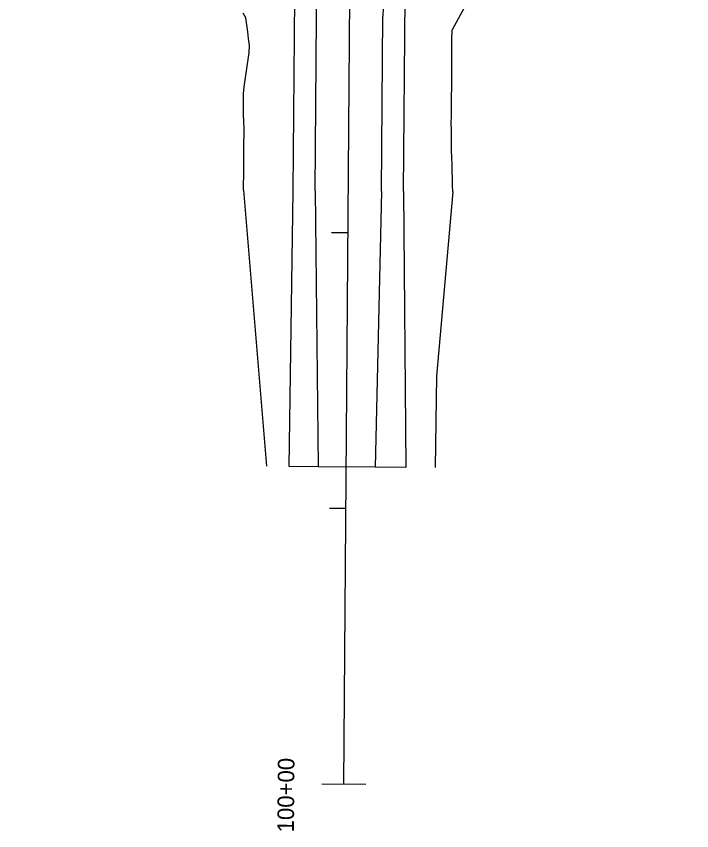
# Model space of a CAD drawing. Extents: x 1311167 to 1314552, y 2087587 to 2090602.
# Drawn here: x 1313869.5 to 1314114.4, y 2087983.8 to 2088279.1 of the extents above; entities that cross this region are included whole.
import ezdxf

# ---------------------------------------------------------------- set-up
doc = ezdxf.new("R2010")
doc.units = 0
for name, color, linetype in [('R_Bridge', 7, 'Continuous'), ('R_Horz Alg Stationing', 7, 'Continuous'), ('R_Proposed Road', 7, 'Continuous'), ('S_EDGE_CONCRETE', 7, 'Continuous'), ('S_EDGE_PAVEMENT', 7, 'Continuous'), ('S_PAVEMENT_CROWN', 7, 'Continuous')]:
    doc.layers.add(name, color=color, linetype=linetype)

msp = doc.modelspace()

# ---------------------------------------------------------------- linework, layer by layer
at = {"layer": 'R_Bridge'}
for points in [[(1313983.85, 2088200.74), (1313989.85, 2088200.69)], [(1313983.08, 2088100.74), (1313989.08, 2088100.7)], [(1313980.32, 2088000.76), (1313996.32, 2088000.64)]]:
    msp.add_lwpolyline(points, dxfattribs=at)
at = {"layer": 'R_Horz Alg Stationing'}
msp.add_line((1313988.32, 2088000.7), (1313997.14, 2089155.24), dxfattribs=at)
at = {"layer": 'R_Proposed Road'}
msp.add_line((1313988.32, 2088000.7), (1313992.17, 2088504.92), dxfattribs=at)
at = {"layer": 'S_EDGE_CONCRETE'}
for p, q in [((1314035.5, 2088288.69), (1314027.56, 2088274.13)), ((1313951.88, 2088215.98), (1313960.25, 2088115.92))]:
    msp.add_line(p, q, dxfattribs=at)
for points in [[(1313951.88, 2088215.98), (1313951.97, 2088218.48), (1313951.99, 2088220.98), (1313952.02, 2088223.48), (1313952.04, 2088225.98), (1313952.06, 2088228.48), (1313952.08, 2088230.98), (1313952.1, 2088233.48), (1313952.12, 2088235.98), (1313952.13, 2088238.48), (1313952.02, 2088240.98), (1313951.95, 2088243.48), (1313951.96, 2088245.98), (1313951.96, 2088248.48), (1313951.97, 2088250.98), (1313952.12, 2088253.48), (1313952.49, 2088255.98), (1313952.86, 2088258.48), (1313953.22, 2088260.98), (1313953.58, 2088263.47), (1313953.94, 2088265.97), (1313954.1, 2088268.47), (1313953.78, 2088270.97), (1313953.47, 2088273.47), (1313953.15, 2088275.98), (1313952.83, 2088278.48), (1313951.77, 2088280.22)], [(1314027.83, 2088215.4), (1314027.75, 2088217.9), (1314027.67, 2088220.41), (1314027.6, 2088222.91), (1314027.53, 2088225.41), (1314027.45, 2088227.91), (1314027.38, 2088230.41), (1314027.35, 2088232.91), (1314027.32, 2088235.41), (1314027.29, 2088237.91), (1314027.27, 2088240.41), (1314027.3, 2088242.91), (1314027.33, 2088245.41), (1314027.36, 2088247.91), (1314027.4, 2088250.41), (1314027.43, 2088252.91), (1314027.47, 2088255.41), (1314027.49, 2088257.91), (1314027.49, 2088260.41), (1314027.5, 2088262.91), (1314027.5, 2088265.41), (1314027.51, 2088267.91), (1314027.52, 2088270.41), (1314027.56, 2088274.13)], [(1314027.83, 2088215.4), (1314021.86, 2088148.65), (1314021.38, 2088115.45)]]:
    msp.add_lwpolyline(points, dxfattribs=at)
at = {"layer": 'S_EDGE_PAVEMENT'}
for p, q in [((1313969.96, 2088215.85), (1313970.61, 2088300.36)), ((1314009.96, 2088215.54), (1314010.61, 2088300.74)), ((1313968.44, 2088115.85), (1313969.96, 2088215.85)), ((1314009.96, 2088215.54), (1314010.82, 2088115.53)), ((1313979.04, 2088115.77), (1313968.44, 2088115.85)), ((1314010.82, 2088115.53), (1313999.62, 2088115.62))]:
    msp.add_line(p, q, dxfattribs=at)
at = {"layer": 'S_PAVEMENT_CROWN'}
for p, q in [((1313977.96, 2088215.79), (1313978.44, 2088278.57)), ((1314001.96, 2088215.6), (1314002.45, 2088279.08)), ((1313977.96, 2088215.79), (1313979.04, 2088115.77)), ((1314001.96, 2088215.6), (1313999.62, 2088115.62)), ((1313999.62, 2088115.62), (1313979.04, 2088115.77))]:
    msp.add_line(p, q, dxfattribs=at)
for centre, start, end in [((1313853.45, 2088279.53), 359.5625, 82.6016), ((1314127.44, 2088278.12), 95.9728, 179.5625)]:
    msp.add_arc(centre, 125, start, end, dxfattribs=at)

# ---------------------------------------------------------------- texts
at = {"layer": 'R_Bridge'}
msp.add_text('100+00', height=6, rotation=89.5625, dxfattribs=at).set_placement((1313970.19, 2087983.19))

doc.saveas('drawing.dxf')
